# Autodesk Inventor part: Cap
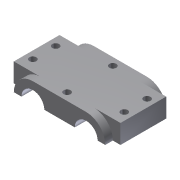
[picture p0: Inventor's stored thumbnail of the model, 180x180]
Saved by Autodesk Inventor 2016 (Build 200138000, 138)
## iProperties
Shininess: 77.0
Length Units: 11269
Angle Units: 11279
Time Units: 11290
Mass Units: 11283
Length Display Precision: 3
Angle Display Precision: 2
Created: 2002-02
Part Number: Cap
Document SubType Name: Modeling
Designer: ***
Density: 1 g/cm^3
Material: Generic
Appearance: Default
Density: 0.0
Volumn: 0.0
Area: 0.0
PropertySet Name: Model Information
Control State: 0
Master: False
Checked Out: False
Author: ***
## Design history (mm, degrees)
sketch "Sketch2"
  geometry: L1 (-17.5, 12.5)-(17.5, 12.5); L2 (30, 0)-(25, 0); L3 (10, 0)-(-10, 0); L4 (-25, 0)-(-30, 0); A1 r 12.5 centre (-17.5, 0) between (-17.5, 12.5) and (-30, 0); A2 r 12.5 centre (17.5, 0) between (30, 0) and (17.5, 12.5); A3 r 7.5 centre (17.5, 0) between (25, 0) and (10, 0); A4 r 7.5 centre (-17.5, 0) between (-10, 0) and (-25, 0)
  constraints: 8 end point, 8 point on circle, 4 centre point, 3 horizontal, 3 parallel, 2 coincident, 2 equal radius, 2 tangent
  dimensions: "d0" = 12.5 radius of A1; "d1" = 7.5 radius of A4; "d2" = 35 distance of A1.centre A2.centre; "d3" = 12.5 distance between parallel lines of L1 L3
extrude "Extrusion1" new body sketch "Sketch2" stored distance "d4" = 40; taper "d5" = 0 deg
workplane "Work Plane1"
sketch "Sketch3"
  geometry: L1 (-15, 12.5)-(15, 12.5); L2 (15, 12.5)-(15, 0); L3 (15, 0)-(-15, 0); L4 (-15, 0)-(-15, 12.5); L5 (-20, 0)-(20, 0) reference; L6 (-20, 12.5)-(20, 12.5) reference; L7 (20, 12.5)-(20, 0) reference
  constraints: 8 end point, 2 collinear, 2 parallel, 1 horizontal, 1 perpendicular
  dimensions: "d7" = 30 distance of L2.end L3.end; "d8" = 5 distance between parallel lines of L7 L2
extrude "Extrusion2" join sketch "Sketch3" stored distance "d9" = 40; taper "d10" = 0 deg
mirror "Mirror1"
sketch "Sketch4"
  geometry: L1 (-17.5, -35)-(0, -35) reference; L2 (-17.5, -35)-(-17.5, -5) reference; 1 further point
  dimensions: "d12" = 7.5 distance from line of L1 point (-12.5, -27.5); "d13" = 5 distance from line of L2 point (-12.5, -27.5)
hole "Hole1" sketch "Sketch4" at (-12.5, -27.5) diameter "d14" = 4.5; stored, may be unused: countersink angle "d18" = 82 deg, drill point angle "d20" = 118 deg; dims "d15" = 6, "d16" = 4, "d17" = 2, "d19" = 8
pattern_linear "Rectangular Pattern1" dims "d23" = 60, "d26" = 15
sketch "Sketch5"
  geometry: L1 (0, -40)-(35, -40) reference; L2 (-17.5, -35)-(-17.5, -5) reference; 1 further point
  dimensions: "d27" = 5 distance from line of L1 point (17.5, -35); "d28" = 35 distance from line of L2 point (17.5, -35)
hole "Hole2" sketch "Sketch5" at (17.5, -35) diameter "d29" = 4.5; stored, may be unused: countersink angle "d33" = 82 deg, drill point angle "d35" = 118 deg; dims "d30" = 6, "d31" = 4, "d32" = 2, "d34" = 8
pattern_linear "Rectangular Pattern2" dims "d38" = 30
body "Solid1"
other parameters: "d11" = 35
